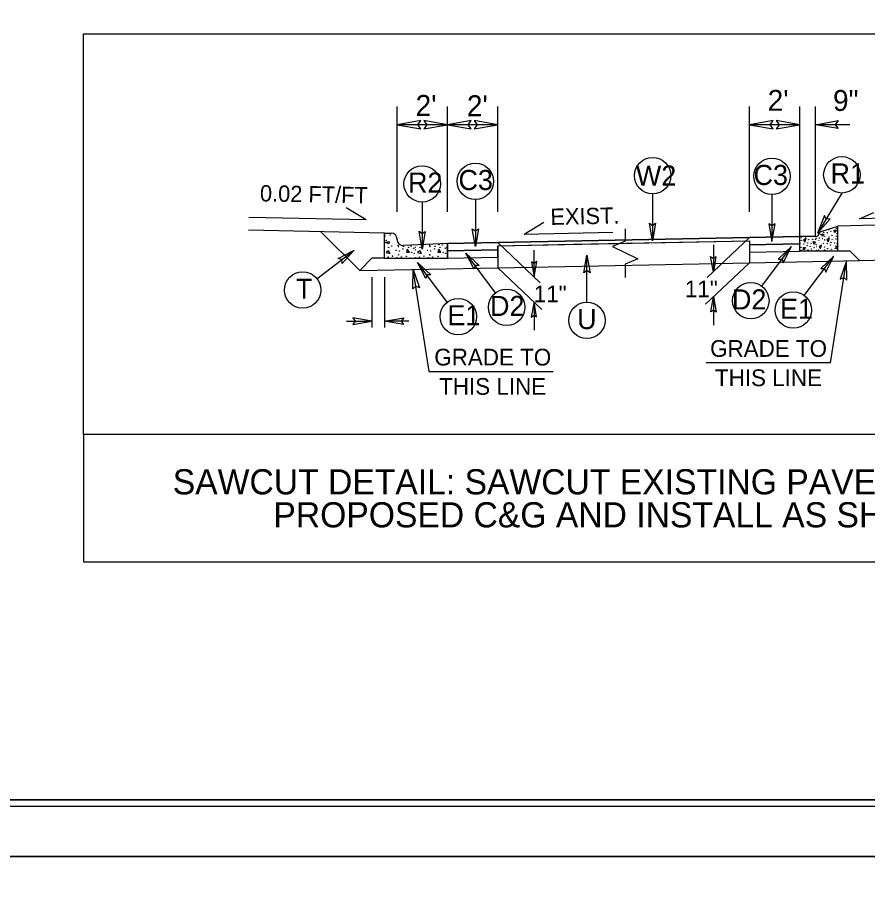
# Model space of a CAD drawing. Extents: x 2320980 to 2456309, y 595047 to 606177.
# Drawn here: x 2455843.3 to 2455910.9, y 597396.6 to 597465.3 of the extents above; entities that cross this region are included whole.
import ezdxf

# ---------------------------------------------------------------- set-up
doc = ezdxf.new("R2010")
doc.units = 0
for name, color, linetype in [('Old_Level_1', 7, 'Continuous'), ('Old_Level_11', 7, 'Continuous'), ('Old_Level_21', 7, 'Continuous'), ('Old_Level_9', 7, 'Continuous'), ('Prop Dimension', 7, 'Continuous'), ('Prop Dimension Text', 7, 'Continuous'), ('Prop Shade Heavy', 7, 'Continuous'), ('Prop Terminator CELL', 7, 'Continuous'), ('Sheet Plan CELL', 7, 'Continuous'), ('Sheet Plot Border Inside CELL', 7, 'Continuous'), ('Sheet Plot Border Outside CELL', 7, 'Continuous'), ('Typical Berm CELL', 7, 'Continuous'), ('Typical Berm Information CELL', 7, 'Continuous'), ('Typical Curb CELL', 7, 'Continuous'), ('Typical ID Circle CELL', 7, 'Continuous'), ('Typical Pavement Slope CELL', 7, 'Continuous'), ('Typical Pavement Slope Information CELL', 7, 'Continuous'), ('Typical Terminator CELL', 7, 'Continuous'), ('Typical Text General CELL', 7, 'Continuous'), ('Typical Text ID Circle CELL', 7, 'Continuous')]:
    doc.layers.add(name, color=color, linetype=linetype)

msp = doc.modelspace()

# ---------------------------------------------------------------- linework, layer by layer
at = {"layer": 'Old_Level_1'}
for p, q in [((2455907.196, 597448.232), (2455908.496, 597448.666)), ((2455908.23, 597448.34), (2455908.404, 597448.34)), ((2455908.24, 597448.166), (2455908.23, 597448.34)), ((2455908.404, 597448.34), (2455908.24, 597448.166)), ((2455908.496, 597446.666), (2455908.496, 597448.666)), ((2455905.495, 597446.666), (2455905.495, 597447.832)), ((2455906.73, 597447.832), (2455905.495, 597447.832)), ((2455905.805, 597447.578), (2455905.971, 597447.696)), ((2455905.887, 597447.396), (2455905.805, 597447.578)), ((2455905.971, 597447.696), (2455905.887, 597447.396)), ((2455907.244, 597448.028), (2455907.418, 597448.028)), ((2455907.254, 597447.854), (2455907.244, 597448.028)), ((2455907.418, 597448.028), (2455907.254, 597447.854)), ((2455907.664, 597447.61), (2455907.83, 597447.728)), ((2455907.746, 597447.426), (2455907.664, 597447.61)), ((2455907.83, 597447.728), (2455907.746, 597447.426)), ((2455905.771, 597446.956), (2455905.945, 597446.956)), ((2455905.781, 597446.782), (2455905.771, 597446.956)), ((2455905.945, 597446.956), (2455905.781, 597446.782)), ((2455906.552, 597447.438), (2455906.698, 597447.41)), ((2455906.624, 597447.19), (2455906.552, 597447.438)), ((2455906.698, 597447.41), (2455906.624, 597447.19)), ((2455907.208, 597447.144), (2455907.026, 597447.044)), ((2455907.026, 597447.044), (2455907.144, 597446.88)), ((2455907.144, 597446.88), (2455907.208, 597447.144)), ((2455908.35, 597447.09), (2455908.496, 597447.062)), ((2455908.422, 597446.842), (2455908.35, 597447.09)), ((2455908.496, 597447.062), (2455908.422, 597446.842)), ((2455908.496, 597446.666), (2455905.495, 597446.666)), ((2455910.243, 597445.927), (2455919.229, 597446.107))]:
    msp.add_line(p, q, dxfattribs=at)
for centre in [(2455907.785, 597448.378), (2455907.963, 597448.261), (2455908.104, 597448.514), (2455908.392, 597448.49), (2455905.599, 597447.77), (2455905.953, 597447.807), (2455906.2, 597447.578), (2455906.501, 597447.606), (2455906.519, 597447.825), (2455906.738, 597447.615), (2455906.77, 597447.674), (2455907.044, 597447.72), (2455907.111, 597448.006), (2455907.291, 597447.665), (2455907.391, 597448.176), (2455907.428, 597447.848), (2455907.474, 597447.573), (2455907.665, 597448.131), (2455907.812, 597447.838), (2455908.049, 597447.939), (2455908.058, 597447.61), (2455908.36, 597447.637), (2455908.378, 597447.857), (2455908.444, 597448.056), (2455905.515, 597447.259), (2455905.578, 597446.985), (2455905.615, 597447.542), (2455905.807, 597447.25), (2455906.081, 597447.122), (2455906.108, 597447.314), (2455906.307, 597447.052), (2455906.382, 597447.286), (2455906.625, 597446.95), (2455906.784, 597447.204), (2455906.816, 597447.044), (2455906.999, 597447.519), (2455907.373, 597447.29), (2455907.437, 597447.016), (2455907.665, 597447.281), (2455907.699, 597446.879), (2455907.939, 597447.153), (2455907.967, 597447.345), (2455908.241, 597447.318), (2455908.287, 597446.888), (2455908.452, 597447.286), (2455905.606, 597446.738), (2455905.925, 597446.689), (2455906.136, 597446.774), (2455906.411, 597446.705), (2455906.428, 597446.857), (2455906.816, 597446.733), (2455906.971, 597446.761), (2455907.465, 597446.77), (2455907.881, 597446.705), (2455907.994, 597446.806)]:
    msp.add_circle(centre, 0.0128, dxfattribs=at)
for centre, radius, start, end in [((2455906.73, 597448.124), 0.292, 270, 343.28105), ((2455907.288, 597447.957), 0.292, 108.43495, 163.28105), ((2455908.46, 597446.678), 0.0128, 25.75843, 152.96144)]:
    msp.add_arc(centre, radius, start, end, dxfattribs=at)
at = {"layer": 'Old_Level_11'}
for points in [[(2455848.572, 597463.948), (2455935.639, 597463.948), (2455935.639, 597432.095), (2455848.572, 597432.095)], [(2455848.572, 597421.98), (2455935.639, 597421.98), (2455935.639, 597432.095), (2455848.572, 597432.095)]]:
    msp.add_lwpolyline(points, close=True, dxfattribs=at)
at = {"layer": 'Old_Level_21'}
for p, q in [((2455905.495, 597447.832), (2455905.495, 597458.171)), ((2455906.73, 597447.832), (2455906.73, 597458.171)), ((2455909.46, 597456.724), (2455906.73, 597456.724)), ((2455907.928, 597437.811), (2455909.19, 597445.906)), ((2455876.034, 597437.122), (2455874.772, 597445.218)), ((2455907.928, 597437.811), (2455898.056, 597437.811)), ((2455876.034, 597437.122), (2455885.906, 597437.122))]:
    msp.add_line(p, q, dxfattribs=at)
at = {"layer": 'Old_Level_9'}
msp.add_line((2455881.495, 597445.352), (2455901.495, 597445.752), dxfattribs=at)
at = {"layer": 'Prop Dimension'}
for p, q in [((2455873.495, 597449.792), (2455873.495, 597458.171)), ((2455877.495, 597449.792), (2455877.495, 597458.171)), ((2455881.495, 597449.792), (2455881.495, 597458.171)), ((2455901.495, 597449.792), (2455901.495, 597458.171)), ((2455877.495, 597456.724), (2455873.495, 597456.724)), ((2455881.495, 597456.724), (2455877.495, 597456.724)), ((2455905.495, 597456.724), (2455901.495, 597456.724)), ((2455901.495, 597447.752), (2455898.118, 597444.569)), ((2455881.495, 597447.352), (2455884.873, 597444.169)), ((2455898.62, 597447.164), (2455898.62, 597445.164)), ((2455884.371, 597446.764), (2455884.371, 597444.764)), ((2455901.495, 597445.752), (2455897.991, 597442.449)), ((2455881.495, 597445.352), (2455885, 597442.049)), ((2455871.496, 597444.606), (2455871.496, 597440.606)), ((2455872.496, 597444.606), (2455872.496, 597440.606)), ((2455898.619, 597443.041), (2455898.619, 597440.79)), ((2455884.372, 597442.641), (2455884.372, 597440.39)), ((2455869.465, 597441.106), (2455871.496, 597441.106)), ((2455874.438, 597441.106), (2455872.496, 597441.106))]:
    msp.add_line(p, q, dxfattribs=at)
at = {"layer": 'Prop Dimension Text'}
msp.add_line((2455908.828, 597451.294), (2455906.898, 597448.104), dxfattribs=at)
msp.add_lwpolyline([(2455916.081, 597449.41), (2455910.225, 597449.249), (2455911.362, 597449.738)], dxfattribs=at)
at = {"layer": 'Prop Shade Heavy'}
for p, q in [((2455905.495, 597447.832), (2455877.495, 597447.272)), ((2455905.5, 597447.582), (2455905.495, 597447.832)), ((2455877.495, 597447.272), (2455877.495, 597446.706))]:
    msp.add_line(p, q, dxfattribs=at)
msp.add_lwpolyline([(2455877.495, 597446.706), (2455881.495, 597446.786), (2455881.495, 597447.102), (2455887.495, 597447.222), (2455901.495, 597447.502), (2455901.495, 597447.186), (2455905.495, 597447.266), (2455905.5, 597447.582)], dxfattribs=at)
at = {"layer": 'Prop Terminator CELL'}
for points in [[(2455898.825, 597446.238), (2455898.619, 597445.041), (2455898.406, 597446.244), (2455898.619, 597446.091)], [(2455884.166, 597445.838), (2455884.372, 597444.641), (2455884.585, 597445.844), (2455884.372, 597445.691)], [(2455898.412, 597441.844), (2455898.619, 597443.041), (2455898.831, 597441.837), (2455898.619, 597441.99)], [(2455884.578, 597441.444), (2455884.372, 597442.641), (2455884.159, 597441.437), (2455884.372, 597441.59)]]:
    msp.add_lwpolyline(points, close=True, dxfattribs=at)
at = {"layer": 'Sheet Plan CELL'}
for points in [[(2455742.104, 597403.076), (2455742.099, 597613.071), (2456002.097, 597613.079), (2456002.099, 597583.066), (2456042.107, 597583.064), (2456042.107, 597403.076)], [(2456042.112, 597613.076), (2455742.104, 597613.076), (2455742.104, 597403.076), (2456042.107, 597403.076)]]:
    msp.add_lwpolyline(points, close=True, dxfattribs=at)
at = {"layer": 'Sheet Plot Border Inside CELL'}
msp.add_lwpolyline([(2455711.407, 597402.574), (2456044.604, 597402.576), (2456044.607, 597613.574), (2455711.407, 597613.574)], close=True, dxfattribs=at)
at = {"layer": 'Sheet Plot Border Outside CELL'}
for points in [[(2455708.807, 597398.574), (2456045.507, 597398.574), (2456045.507, 597617.574), (2455708.807, 597617.574)], [(2455708.807, 597179.574), (2456045.507, 597179.574), (2456045.507, 597398.574), (2455708.807, 597398.574)]]:
    msp.add_lwpolyline(points, close=True, dxfattribs=at)
at = {"layer": 'Typical Berm CELL'}
msp.add_line((2455872.496, 597448.105), (2455861.683, 597448.331), dxfattribs=at)
at = {"layer": 'Typical Berm Information CELL'}
for q in [(2455869.459, 597450.113), (2455861.704, 597449.353)]:
    msp.add_line((2455871.025, 597449.167), q, dxfattribs=at)
at = {"layer": 'Typical Curb CELL'}
for p, q in [((2455872.496, 597446.106), (2455872.496, 597448.105)), ((2455872.496, 597448.105), (2455873.017, 597448.105)), ((2455873.496, 597447.605), (2455873.496, 597447.626)), ((2455872.569, 597447.349), (2455872.877, 597447.439)), ((2455872.844, 597447.257), (2455872.569, 597447.349)), ((2455872.877, 597447.439), (2455872.844, 597447.257)), ((2455877.495, 597447.272), (2455873.995, 597447.126)), ((2455877.495, 597446.106), (2455877.495, 597447.272)), ((2455872.821, 597446.712), (2455872.615, 597446.562)), ((2455872.615, 597446.562), (2455872.946, 597446.482)), ((2455872.946, 597446.482), (2455872.821, 597446.712)), ((2455874.304, 597446.824), (2455874.235, 597446.597)), ((2455874.235, 597446.597), (2455874.475, 597446.585)), ((2455874.475, 597446.585), (2455874.304, 597446.824)), ((2455875.319, 597446.712), (2455875.112, 597446.562)), ((2455875.112, 597446.562), (2455875.444, 597446.482)), ((2455875.444, 597446.482), (2455875.319, 597446.712)), ((2455876.802, 597446.824), (2455876.733, 597446.597)), ((2455876.733, 597446.597), (2455876.975, 597446.585)), ((2455876.975, 597446.585), (2455876.802, 597446.824)), ((2455872.496, 597446.106), (2455877.495, 597446.106))]:
    msp.add_line(p, q, dxfattribs=at)
for centre in [(2455872.523, 597447.885), (2455872.957, 597447.954), (2455872.626, 597447.52), (2455872.82, 597446.974), (2455873.06, 597447.075), (2455873.574, 597447.132), (2455873.608, 597447.031), (2455874.019, 597447.063), (2455874.407, 597446.985), (2455874.601, 597447.071), (2455874.818, 597446.905), (2455874.93, 597446.974), (2455875.318, 597446.974), (2455875.558, 597447.075), (2455876.072, 597447.132), (2455876.106, 597447.031), (2455876.517, 597447.063), (2455876.814, 597447.189), (2455876.905, 597446.985), (2455877.099, 597447.155), (2455877.316, 597446.905), (2455877.428, 597446.974), (2455872.786, 597446.197), (2455873.128, 597446.277), (2455873.413, 597446.745), (2455873.596, 597446.38), (2455873.665, 597446.688), (2455873.825, 597446.209), (2455873.962, 597446.86), (2455874.236, 597446.254), (2455874.658, 597446.585), (2455874.85, 597446.494), (2455874.964, 597446.78), (2455875.284, 597446.197), (2455875.626, 597446.277), (2455875.912, 597446.745), (2455876.095, 597446.38), (2455876.163, 597446.688), (2455876.323, 597446.209), (2455876.46, 597446.86), (2455876.734, 597446.254), (2455877.156, 597446.585), (2455877.348, 597446.494), (2455877.462, 597446.78), (2455873.482, 597446.152), (2455874.555, 597446.118), (2455874.976, 597446.163), (2455875.98, 597446.152), (2455877.053, 597446.118), (2455877.474, 597446.163)]:
    msp.add_circle(centre, 0.016, dxfattribs=at)
for centre, start, end in [((2455873.017, 597447.626), 0, 90), ((2455873.975, 597447.605), 180, 272.38446)]:
    msp.add_arc(centre, 0.479, start, end, dxfattribs=at)
at = {"layer": 'Typical ID Circle CELL'}
for p, q in [((2455893.793, 597451.225), (2455893.793, 597447.484)), ((2455903.274, 597451.179), (2455903.274, 597447.438)), ((2455875.487, 597450.572), (2455875.487, 597446.832)), ((2455879.717, 597450.779), (2455879.717, 597447.038)), ((2455902.465, 597443.892), (2455904.828, 597447.031)), ((2455867.131, 597444.472), (2455870.088, 597446.763)), ((2455881.324, 597443.373), (2455878.96, 597446.512)), ((2455888.573, 597442.622), (2455888.573, 597446.363)), ((2455905.838, 597443.15), (2455908.201, 597446.288)), ((2455877.486, 597442.631), (2455875.123, 597445.77))]:
    msp.add_line(p, q, dxfattribs=at)
for centre in [(2455893.793, 597452.672), (2455903.274, 597452.626), (2455908.828, 597452.741), (2455875.487, 597452.019), (2455879.717, 597452.226), (2455865.987, 597443.586), (2455901.594, 597442.735), (2455882.195, 597442.217), (2455878.357, 597441.475), (2455904.967, 597441.993), (2455888.573, 597441.175)]:
    msp.add_circle(centre, 1.447, dxfattribs=at)
at = {"layer": 'Typical Pavement Slope CELL'}
for p, q in [((2455919.229, 597448.911), (2455908.496, 597448.666)), ((2455870.523, 597445.133), (2455867.446, 597448.211)), ((2455877.495, 597447.272), (2455905.495, 597447.832)), ((2455881.495, 597447.102), (2455901.495, 597447.502)), ((2455881.495, 597447.102), (2455881.495, 597445.352)), ((2455901.495, 597447.502), (2455901.495, 597445.752)), ((2455901.495, 597447.186), (2455905.495, 597447.266)), ((2455905.495, 597447.266), (2455901.495, 597447.186)), ((2455901.495, 597447.186), (2455901.495, 597446.586)), ((2455905.495, 597446.666), (2455905.495, 597447.266)), ((2455877.495, 597446.706), (2455881.495, 597446.786)), ((2455881.495, 597446.786), (2455877.495, 597446.706)), ((2455877.495, 597446.706), (2455877.495, 597446.106)), ((2455881.495, 597446.186), (2455881.495, 597446.786)), ((2455901.495, 597446.586), (2455905.495, 597446.666)), ((2455901.495, 597446.586), (2455905.495, 597446.666)), ((2455909.496, 597446.666), (2455908.496, 597446.666)), ((2455909.496, 597446.666), (2455910.243, 597445.927)), ((2455870.523, 597445.133), (2455871.496, 597446.106)), ((2455872.496, 597446.106), (2455871.496, 597446.106)), ((2455877.495, 597446.106), (2455881.495, 597446.186)), ((2455877.495, 597446.106), (2455881.495, 597446.186)), ((2455901.495, 597445.752), (2455910.243, 597445.927)), ((2455870.523, 597445.133), (2455881.495, 597445.352))]:
    msp.add_line(p, q, dxfattribs=at)
at = {"layer": 'Typical Pavement Slope Information CELL'}
for p, q in [((2455883.588, 597448.029), (2455885.154, 597448.976)), ((2455891.617, 597448.456), (2455891.617, 597447.468)), ((2455883.588, 597448.029), (2455890.641, 597448.171)), ((2455891.617, 597447.468), (2455890.617, 597447.053)), ((2455890.617, 597447.053), (2455892.617, 597446.063)), ((2455892.617, 597446.063), (2455891.617, 597445.649)), ((2455891.617, 597445.649), (2455891.617, 597444.589))]:
    msp.add_line(p, q, dxfattribs=at)
at = {"layer": 'Typical Terminator CELL'}
for points in [[(2455875.37, 597457.047), (2455873.495, 597456.724), (2455875.38, 597456.391), (2455875.141, 597456.724)], [(2455875.621, 597456.402), (2455877.495, 597456.724), (2455875.61, 597457.058), (2455875.85, 597456.724)], [(2455879.37, 597457.047), (2455877.495, 597456.724), (2455879.38, 597456.391), (2455879.141, 597456.724)], [(2455879.621, 597456.402), (2455881.495, 597456.724), (2455879.61, 597457.058), (2455879.85, 597456.724)], [(2455903.37, 597457.047), (2455901.495, 597456.724), (2455903.38, 597456.391), (2455903.141, 597456.724)], [(2455903.621, 597456.402), (2455905.495, 597456.724), (2455903.61, 597457.058), (2455903.85, 597456.724)], [(2455908.525, 597456.415), (2455906.73, 597456.724), (2455908.535, 597457.044), (2455908.306, 597456.724)], [(2455907.452, 597449.517), (2455906.898, 597448.104), (2455907.905, 597449.253), (2455907.578, 597449.228)], [(2455879.96, 597448.449), (2455879.717, 597447.038), (2455879.466, 597448.457), (2455879.717, 597448.277)], [(2455894.036, 597448.895), (2455893.793, 597447.484), (2455893.542, 597448.903), (2455893.793, 597448.723)], [(2455903.031, 597448.849), (2455903.274, 597447.438), (2455903.525, 597448.857), (2455903.274, 597448.677)], [(2455875.73, 597448.243), (2455875.487, 597446.832), (2455875.236, 597448.25), (2455875.487, 597448.07)], [(2455904.174, 597445.757), (2455904.828, 597447.031), (2455903.775, 597446.048), (2455904.083, 597446.041)], [(2455868.824, 597446.091), (2455870.088, 597446.763), (2455869.12, 597445.696), (2455869.109, 597446.004)], [(2455879.615, 597445.239), (2455878.96, 597446.512), (2455880.014, 597445.53), (2455879.705, 597445.523)], [(2455888.33, 597444.952), (2455888.573, 597446.363), (2455888.823, 597444.944), (2455888.573, 597445.124)], [(2455907.547, 597445.015), (2455908.201, 597446.288), (2455907.148, 597445.306), (2455907.457, 597445.299)], [(2455875.777, 597444.497), (2455875.123, 597445.77), (2455876.176, 597444.788), (2455875.867, 597444.781)], [(2455909.214, 597444.366), (2455909.19, 597445.906), (2455908.688, 597444.44), (2455908.984, 597444.59)], [(2455874.748, 597443.678), (2455874.772, 597445.218), (2455875.274, 597443.752), (2455874.978, 597443.902)], [(2455869.979, 597440.844), (2455871.496, 597441.106), (2455869.97, 597441.375), (2455870.164, 597441.106)], [(2455874.014, 597440.844), (2455872.496, 597441.106), (2455874.022, 597441.375), (2455873.828, 597441.106)]]:
    msp.add_lwpolyline(points, close=True, dxfattribs=at)

# ---------------------------------------------------------------- texts
at = {"layer": 'Old_Level_21'}
for s, height, p in [('9"', 1.6625, (2455908.126, 597457.816)), ('GRADE TO', 1.33, (2455898.361, 597438.277)), ('GRADE TO', 1.33, (2455876.45, 597437.589)), ('THIS LINE', 1.33, (2455898.748, 597435.95)), ('THIS LINE', 1.33, (2455876.837, 597435.261))]:
    msp.add_text(s, height=height, dxfattribs=at).set_placement(p)
for s, p in [("SAWCUT DETAIL: SAWCUT EXISTING PAVEMENT 2' FROM", (2455855.674, 597427.349)), ('PROPOSED C&G AND INSTALL AS SHOWN', (2455863.667, 597424.727))]:
    msp.add_text(s, height=2, rotation=360, dxfattribs=at).set_placement(p)
at = {"layer": 'Typical Pavement Slope Information CELL'}
for s, rotation, p in [('0.02 FT/FT', 358.85426, (2455862.589, 597450.633)), ('EXIST.', 1.14574, (2455885.686, 597448.758))]:
    msp.add_text(s, height=1.2952, rotation=rotation, dxfattribs=at).set_placement(p)
for p in [(2455896.358, 597443.012), (2455884.354, 597442.612)]:
    msp.add_text('11"', height=1.33, dxfattribs=at).set_placement(p)
at = {"layer": 'Typical Text General CELL'}
for p in [(2455902.937, 597457.826), (2455874.967, 597457.421), (2455879.04, 597457.397)]:
    msp.add_text("2'", height=1.6625, dxfattribs=at).set_placement(p)
at = {"layer": 'Typical Text ID Circle CELL'}
for s, p in [('C3', (2455878.373, 597451.53)), ('W2', (2455892.466, 597451.879)), ('C3', (2455901.813, 597451.93)), ('R1', (2455907.931, 597452.045)), ('R2', (2455874.361, 597451.323)), ('T', (2455865.457, 597442.89)), ('D2', (2455900.096, 597442.039)), ('D2', (2455880.88, 597441.521)), ('E1', (2455903.915, 597441.297)), ('E1', (2455877.489, 597440.779)), ('U', (2455887.798, 597440.479))]:
    msp.add_text(s, height=1.6, dxfattribs=at).set_placement(p)

doc.saveas('drawing.dxf')
